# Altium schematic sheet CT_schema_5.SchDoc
size 224 x 182 mm
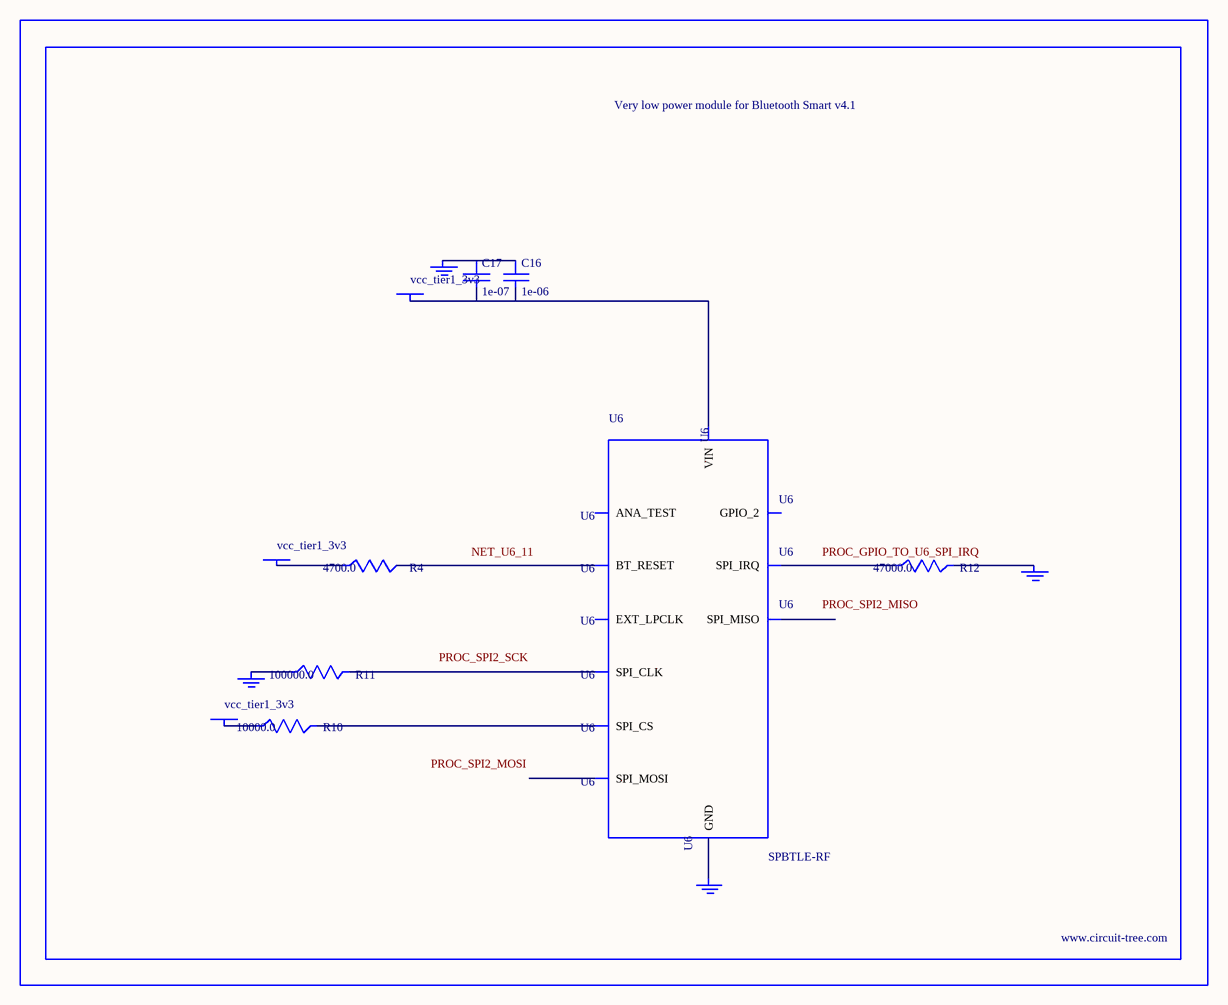
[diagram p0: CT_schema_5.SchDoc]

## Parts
BORDER4  (no value)
C16  1e-06  [C0603]
C17  1e-07  [C0402]
GND_INSTANCE_4_0  (no value)
GND_INSTANCE_4_1  (no value)
GND_INSTANCE_4_2  (no value)
GND_INSTANCE_4_3  (no value)
POWER_INSTANCE_4_0  vcc_tier1_3v3
POWER_INSTANCE_4_1  vcc_tier1_3v3
POWER_INSTANCE_4_2  vcc_tier1_3v3
R4  4700.0  [R0603]
R10  10000.0  [R0603]
R11  100000.0  [R0603]
R12  47000.0  [R0603]
U6  SPBTLE-RF  [XCVR_SPBTLE-RF]

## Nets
NetC16_1: C16.1 C17.1 GND_INSTANCE_4_1.0(GND)
NetC16_2: C16.2 C17.2 POWER_INSTANCE_4_0.0(PWR) U6.5(VIN)
NetGND_INSTANCE_4_0_0: GND_INSTANCE_4_0.0(GND) R12.2
NetGND_INSTANCE_4_2_0: GND_INSTANCE_4_2.0(GND) R11.1
NetGND_INSTANCE_4_3_0: GND_INSTANCE_4_3.0(GND) U6.6(GND)
NetPOWER_INSTANCE_4_1_0: POWER_INSTANCE_4_1.0(PWR) R10.1
NetPOWER_INSTANCE_4_2_0: POWER_INSTANCE_4_2.0(PWR) R4.1
NetR4_2: R4.2 U6.11(BT_RESET)
NetR10_2: R10.2 U6.10(SPI_CS)
NetR11_2: R11.2 U6.7(SPI_CLK)
NetR12_1: R12.1 U6.4(SPI_IRQ)

Not connected (* = marked no-connect by the designer): U6 1(EXT_LPCLK) 2(GPIO_2) 3(ANA_TEST) 8(SPI_MISO) 9(SPI_MOSI)

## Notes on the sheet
- Labels drawn without touching a wire or pin: NET_U6_11, PROC_GPIO_TO_U6_SPI_IRQ, PROC_SPI2_MISO, PROC_SPI2_MOSI, PROC_SPI2_SCK

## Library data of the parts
BORDER4 = BORDER_PAGE4
C16 = C0603C105K3RACTU
C17 = C0402C104K3RACTU
GND_INSTANCE_4_0-GND_INSTANCE_4_3 = GND
POWER_INSTANCE_4_0-POWER_INSTANCE_4_2 = PWR
R4 = RC0603JR-074K7L
R10 = RC0603JR-0710KL
R11 = RC0603JR-07100KL
R12 = RC0603JR-0747KL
